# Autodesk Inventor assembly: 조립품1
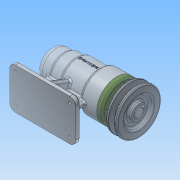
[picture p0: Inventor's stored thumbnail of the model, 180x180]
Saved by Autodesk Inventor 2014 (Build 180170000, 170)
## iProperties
Created: 2016-06
Part Number: 조립품1
Document SubType Name: Assembly
Designer: net
Author: net
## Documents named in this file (12)
- C:\Users\net\Desktop\460607V1010\조립품1.iam
- C:\Users\net\Desktop\460607V1010\V벨트풀리.ipt
- C:\Users\net\Desktop\460607V1010\멈춤나사 M3x8.ipt
- C:\Users\net\Desktop\460607V1010\베어링 6004.ipt
- C:\Users\net\Desktop\460607V1010\베어링 51202.ipt
- C:\Users\net\Desktop\460607V1010\본체.ipt
- C:\Users\net\Desktop\460607V1010\볼트 M4 x 12.ipt
- C:\Users\net\Desktop\460607V1010\어댑터슬리브.ipt
- C:\Users\net\Desktop\460607V1010\오일 실.ipt
- C:\Users\net\Desktop\460607V1010\축.ipt
- C:\Users\net\Desktop\460607V1010\커버.ipt
- C:\Users\net\Desktop\460607V1010\키 5 x 5 x 16.ipt
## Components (6 placed, 2 different names)
1. V벨트풀리:1
2. ISO 4762 M4 x 12:1
3. ISO 4762 M4 x 12:2
4. ISO 4762 M4 x 12:3
5. ISO 4762 M4 x 12:4
6. ISO 4762 M4 x 12:5
